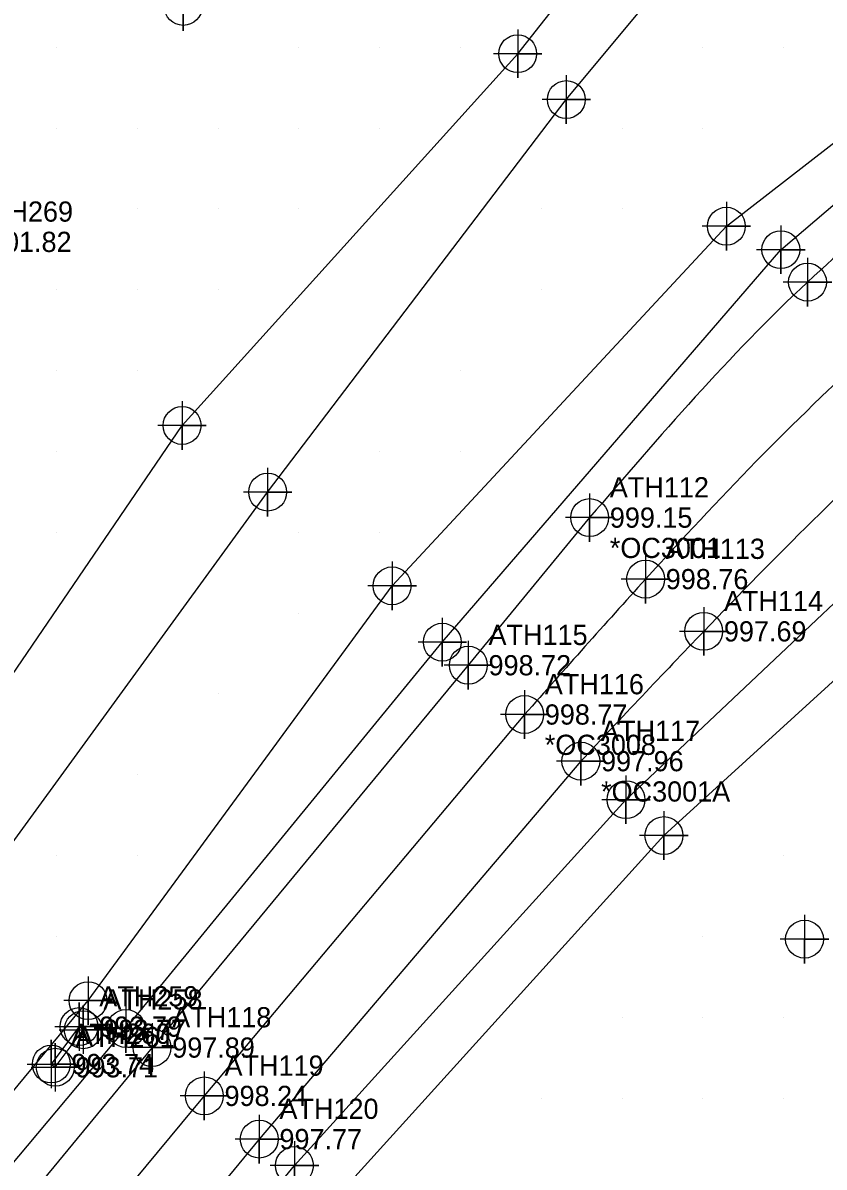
# Model space of a CAD drawing. Extents: x 1116680 to 1117499, y 661040 to 661703.
# Drawn here: x 1116855.8 to 1116955, y 661221.5 to 661363 of the extents above; entities that cross this region are included whole.
import ezdxf

# ---------------------------------------------------------------- set-up
doc = ezdxf.new("R2010")
doc.units = 0
for name, color, linetype in [('Exist DTM Breakline', 7, 'Continuous'), ('Exist DTM Breakline Cogo Point CELL', 7, 'Continuous'), ('Exist DTM Crownline', 7, 'Continuous'), ('Exist DTM Crownline Cogo Comment', 7, 'Continuous'), ('Exist DTM Crownline Cogo Elevation', 7, 'Continuous'), ('Exist DTM Crownline Cogo Number', 7, 'Continuous'), ('Exist DTM Crownline Cogo Point CELL', 7, 'Continuous'), ('Exist DTM QL2 LIDAR Elevation Point', 7, 'Continuous'), ('Exist DTM Regular Point CELL', 7, 'Continuous'), ('Exist DTM Regular Point Cogo Elevation', 7, 'Continuous'), ('Exist DTM Regular Point Cogo Number', 7, 'Continuous'), ('Exist Roads EOP', 7, 'Continuous'), ('Exist Roads EOP Cogo Comment', 7, 'Continuous'), ('Exist Roads EOP Cogo Elevation', 7, 'Continuous'), ('Exist Roads EOP Cogo Number', 7, 'Continuous'), ('Exist Roads EOP Cogo Point CELL', 7, 'Continuous'), ('Exist Structure Major Bridge WW Cogo Elevation', 7, 'Continuous'), ('Exist Structure Major Bridge WW Cogo Number', 7, 'Continuous'), ('Exist Structure Major Bridge WW Cogo Point CELL', 7, 'Continuous')]:
    doc.layers.add(name, color=color, linetype=linetype)

msp = doc.modelspace()

# ---------------------------------------------------------------- linework, layer by layer
at = {"layer": 'Exist DTM Breakline'}
for points in [[(1116759.405, 661157.47), (1116807.255, 661219.832), (1116841.622, 661263.499), (1116875.544, 661313.217), (1116917.082, 661359.208), (1116949.523, 661400.365), (1116973.082, 661430.897), (1117008.611, 661472.228)], [(1116764.746, 661153.381), (1116812.662, 661214.66), (1116849.832, 661255.197), (1116886.132, 661304.973), (1116923.093, 661353.534), (1116959.436, 661397.157), (1116983.43, 661423.245), (1117016.608, 661461.344)], [(1116777.711, 661140.704), (1116828.227, 661198.994), (1116863.907, 661242.056), (1116901.537, 661293.371), (1116942.909, 661337.866), (1116986.207, 661371.481), (1117014.804, 661386.644), (1117027.371, 661386.959)], [(1116764.336, 661115.367), (1116780.79, 661135.76), (1116832.216, 661195.325), (1116868.599, 661238.611), (1116907.746, 661286.411), (1116949.649, 661334.962), (1116977.116, 661358.387), (1117017.083, 661374.758), (1117030.676, 661371.171)], [(1116804.214, 661119.184), (1116852.32, 661176.293), (1116889.45, 661221.661), (1116930.482, 661266.919), (1116979.857, 661313.491), (1117005.659, 661333.608)], [(1116935.96, 661187.155), (1116915.624, 661198.811), (1116892.595, 661215.476), (1116935.176, 661262.478), (1116985.662, 661308.46), (1117011.556, 661329.863)], [(1116863.311, 661238.455), (1116862.795, 661238.847), (1116859.359, 661234.212), (1116859.848, 661233.813), (1116863.311, 661238.455)]]:
    msp.add_lwpolyline(points, dxfattribs=at)
at = {"layer": 'Exist DTM Breakline Cogo Point CELL'}
for points in [[(1116875.69, 661368.058), (1116875.69, 661362.058), (1116875.69, 661365.058), (1116878.69, 661365.058), (1116872.69, 661365.058)], [(1116917.082, 661362.208), (1116917.082, 661356.208), (1116917.082, 661359.208), (1116920.082, 661359.208), (1116914.082, 661359.208)], [(1116923.093, 661356.534), (1116923.093, 661350.534), (1116923.093, 661353.534), (1116926.093, 661353.534), (1116920.093, 661353.534)], [(1116942.909, 661340.866), (1116942.909, 661334.866), (1116942.909, 661337.866), (1116945.909, 661337.866), (1116939.909, 661337.866)], [(1116949.649, 661337.962), (1116949.649, 661331.962), (1116949.649, 661334.962), (1116952.649, 661334.962), (1116946.649, 661334.962)], [(1116875.544, 661316.217), (1116875.544, 661310.217), (1116875.544, 661313.217), (1116878.544, 661313.217), (1116872.544, 661313.217)], [(1116886.132, 661307.973), (1116886.132, 661301.973), (1116886.132, 661304.973), (1116889.132, 661304.973), (1116883.132, 661304.973)], [(1116901.537, 661296.371), (1116901.537, 661290.371), (1116901.537, 661293.371), (1116904.537, 661293.371), (1116898.537, 661293.371)], [(1116907.746, 661289.411), (1116907.746, 661283.411), (1116907.746, 661286.411), (1116910.746, 661286.411), (1116904.746, 661286.411)], [(1116930.482, 661269.919), (1116930.482, 661263.919), (1116930.482, 661266.919), (1116933.482, 661266.919), (1116927.482, 661266.919)], [(1116935.176, 661265.478), (1116935.176, 661259.478), (1116935.176, 661262.478), (1116938.176, 661262.478), (1116932.176, 661262.478)], [(1116863.907, 661245.056), (1116863.907, 661239.056), (1116863.907, 661242.056), (1116866.907, 661242.056), (1116860.907, 661242.056)], [(1116868.599, 661241.611), (1116868.599, 661235.611), (1116868.599, 661238.611), (1116871.599, 661238.611), (1116865.599, 661238.611)], [(1116889.45, 661224.661), (1116889.45, 661218.661), (1116889.45, 661221.661), (1116892.45, 661221.661), (1116886.45, 661221.661)]]:
    msp.add_lwpolyline(points, dxfattribs=at)
for centre in [(1116875.69, 661365.058), (1116917.082, 661359.208), (1116923.093, 661353.534), (1116942.909, 661337.866), (1116949.649, 661334.962), (1116875.544, 661313.217), (1116886.132, 661304.973), (1116901.537, 661293.371), (1116907.746, 661286.411), (1116930.482, 661266.919), (1116935.176, 661262.478), (1116863.907, 661242.056), (1116868.599, 661238.611), (1116889.45, 661221.661)]:
    msp.add_circle(centre, 2.344, dxfattribs=at)
at = {"layer": 'Exist DTM Crownline'}
msp.add_lwpolyline([(1116917.938, 661277.457), (1116878.296, 661230.271), (1116842.354, 661187.006), (1116792.558, 661125.963), (1116776.188, 661106.218)], dxfattribs=at)
msp.add_spline([(1117023.526, 661357.17), (1116985.409, 661341.089), (1116961.036, 661322.674), (1116932.907, 661294.206), (1116917.938, 661277.457)], degree=3, dxfattribs=at)
at = {"layer": 'Exist DTM Crownline Cogo Point CELL'}
for points in [[(1116932.907, 661297.206), (1116932.907, 661291.206), (1116932.907, 661294.206), (1116935.907, 661294.206), (1116929.907, 661294.206)], [(1116917.938, 661280.457), (1116917.938, 661274.457), (1116917.938, 661277.457), (1116920.938, 661277.457), (1116914.938, 661277.457)], [(1116878.296, 661233.271), (1116878.296, 661227.271), (1116878.296, 661230.271), (1116881.296, 661230.271), (1116875.296, 661230.271)]]:
    msp.add_lwpolyline(points, dxfattribs=at)
for centre in [(1116932.907, 661294.206), (1116917.938, 661277.457), (1116878.296, 661230.271)]:
    msp.add_circle(centre, 2.344, dxfattribs=at)
at = {"layer": 'Exist DTM QL2 LIDAR Elevation Point'}
for p, q in [((1116860, 661360), (1116860, 661360)), ((1116890, 661360), (1116890, 661360)), ((1116900, 661360), (1116900, 661360)), ((1116910, 661360), (1116910, 661360)), ((1116940, 661360), (1116940, 661360)), ((1116950, 661360), (1116950, 661360)), ((1116860, 661350), (1116860, 661350)), ((1116870, 661350), (1116870, 661350)), ((1116880, 661350), (1116880, 661350)), ((1116890, 661350), (1116890, 661350)), ((1116900, 661350), (1116900, 661350)), ((1116930, 661350), (1116930, 661350)), ((1116940, 661350), (1116940, 661350)), ((1116860, 661340), (1116860, 661340)), ((1116870, 661340), (1116870, 661340)), ((1116880, 661340), (1116880, 661340)), ((1116890, 661340), (1116890, 661340)), ((1116920, 661340), (1116920, 661340)), ((1116930, 661340), (1116930, 661340)), ((1116860, 661330), (1116860, 661330)), ((1116870, 661330), (1116870, 661330)), ((1116880, 661330), (1116880, 661330)), ((1116920, 661330), (1116920, 661330)), ((1116860, 661320), (1116860, 661320)), ((1116870, 661320), (1116870, 661320)), ((1116910, 661320), (1116910, 661320)), ((1116860, 661310), (1116860, 661310)), ((1116900, 661310), (1116900, 661310)), ((1116910, 661310), (1116910, 661310)), ((1116860, 661300), (1116860, 661300)), ((1116890, 661300), (1116890, 661300)), ((1116900, 661300), (1116900, 661300)), ((1116890, 661290), (1116890, 661290)), ((1116880, 661280), (1116880, 661280)), ((1116870, 661270), (1116870, 661270)), ((1116860, 661260), (1116860, 661260)), ((1116870, 661260), (1116870, 661260)), ((1116950, 661260), (1116950, 661260)), ((1116860, 661250), (1116860, 661250)), ((1116940, 661250), (1116940, 661250)), ((1116950, 661250), (1116950, 661250)), ((1116930, 661240), (1116930, 661240)), ((1116940, 661240), (1116940, 661240)), ((1116950, 661240), (1116950, 661240)), ((1116920, 661230), (1116920, 661230)), ((1116930, 661230), (1116930, 661230)), ((1116940, 661230), (1116940, 661230)), ((1116950, 661230), (1116950, 661230))]:
    msp.add_line(p, q, dxfattribs=at)
at = {"layer": 'Exist DTM Regular Point CELL'}
msp.add_lwpolyline([(1116952.58, 661252.659), (1116952.58, 661246.659), (1116952.58, 661249.659), (1116955.58, 661249.659), (1116949.58, 661249.659)], dxfattribs=at)
msp.add_circle((1116952.58, 661249.659), 2.344, dxfattribs=at)
at = {"layer": 'Exist Roads EOP'}
for points in [[(1116925.984, 661301.817), (1116910.969, 661283.553), (1116871.822, 661236.252), (1116835.673, 661192.44), (1116785.819, 661131.962), (1116768.893, 661111.563)], [(1116924.898, 661271.684), (1116885.096, 661224.926), (1116849.016, 661181.231), (1116799.444, 661121.119), (1116782.519, 661100.642)]]:
    msp.add_lwpolyline(points, dxfattribs=at)
for points in [[(1117026.904, 661368.114), (1116980.178, 661351.152), (1116952.946, 661330.95), (1116925.984, 661301.817)], [(1117018.008, 661346.187), (1116990.857, 661332.639), (1116967.617, 661314.642), (1116940.103, 661287.744), (1116924.898, 661271.684)]]:
    msp.add_spline(points, degree=3, dxfattribs=at)
at = {"layer": 'Exist Roads EOP Cogo Point CELL'}
for points in [[(1116952.946, 661333.95), (1116952.946, 661327.95), (1116952.946, 661330.95), (1116955.946, 661330.95), (1116949.946, 661330.95)], [(1116925.984, 661304.817), (1116925.984, 661298.817), (1116925.984, 661301.817), (1116928.984, 661301.817), (1116922.984, 661301.817)], [(1116940.103, 661290.744), (1116940.103, 661284.744), (1116940.103, 661287.744), (1116943.103, 661287.744), (1116937.103, 661287.744)], [(1116910.969, 661286.553), (1116910.969, 661280.553), (1116910.969, 661283.553), (1116913.969, 661283.553), (1116907.969, 661283.553)], [(1116924.898, 661274.684), (1116924.898, 661268.684), (1116924.898, 661271.684), (1116927.898, 661271.684), (1116921.898, 661271.684)], [(1116871.822, 661239.252), (1116871.822, 661233.252), (1116871.822, 661236.252), (1116874.822, 661236.252), (1116868.822, 661236.252)], [(1116885.096, 661227.926), (1116885.096, 661221.926), (1116885.096, 661224.926), (1116888.096, 661224.926), (1116882.096, 661224.926)]]:
    msp.add_lwpolyline(points, dxfattribs=at)
for centre in [(1116952.946, 661330.95), (1116925.984, 661301.817), (1116940.103, 661287.744), (1116910.969, 661283.553), (1116924.898, 661271.684), (1116871.822, 661236.252), (1116885.096, 661224.926)]:
    msp.add_circle(centre, 2.344, dxfattribs=at)
at = {"layer": 'Exist Structure Major Bridge WW Cogo Point CELL'}
for points in [[(1116859.795, 661238.847), (1116865.795, 661238.847), (1116862.795, 661238.847), (1116862.795, 661241.847), (1116862.795, 661235.847)], [(1116860.311, 661238.455), (1116866.311, 661238.455), (1116863.311, 661238.455), (1116863.311, 661241.455), (1116863.311, 661235.455)], [(1116856.359, 661234.212), (1116862.359, 661234.212), (1116859.359, 661234.212), (1116859.359, 661237.212), (1116859.359, 661231.212)], [(1116856.848, 661233.813), (1116862.848, 661233.813), (1116859.848, 661233.813), (1116859.848, 661236.813), (1116859.848, 661230.813)]]:
    msp.add_lwpolyline(points, dxfattribs=at)
for centre in [(1116862.795, 661238.847), (1116863.311, 661238.455), (1116859.359, 661234.212), (1116859.848, 661233.813)]:
    msp.add_circle(centre, 2.344, dxfattribs=at)

# ---------------------------------------------------------------- texts
at = {"layer": 'Exist DTM Crownline Cogo Comment'}
msp.add_text('*OC3008', height=2.5, dxfattribs=at).set_placement((1116920.438, 661272.457))
at = {"layer": 'Exist DTM Crownline Cogo Elevation'}
for s, p in [('998.76', (1116935.407, 661292.956)), ('998.77', (1116920.438, 661276.207)), ('998.24', (1116880.796, 661229.021))]:
    msp.add_text(s, height=2.5, dxfattribs=at).set_placement(p)
at = {"layer": 'Exist DTM Crownline Cogo Number'}
for s, p in [('ATH113', (1116935.407, 661296.706)), ('ATH116', (1116920.438, 661279.957)), ('ATH119', (1116880.796, 661232.771))]:
    msp.add_text(s, height=2.5, dxfattribs=at).set_placement(p)
at = {"layer": 'Exist DTM Regular Point Cogo Elevation'}
msp.add_text('1001.82', height=2.5, dxfattribs=at).set_placement((1116849.783, 661334.68))
at = {"layer": 'Exist DTM Regular Point Cogo Number'}
msp.add_text('ATH269', height=2.5, dxfattribs=at).set_placement((1116849.783, 661338.43))
at = {"layer": 'Exist Roads EOP Cogo Comment'}
for s, p in [('*OC3001', (1116928.484, 661296.817)), ('*OC3001A', (1116927.398, 661266.684))]:
    msp.add_text(s, height=2.5, dxfattribs=at).set_placement(p)
at = {"layer": 'Exist Roads EOP Cogo Elevation'}
for s, p in [('999.15', (1116928.484, 661300.567)), ('997.69', (1116942.603, 661286.494)), ('998.72', (1116913.469, 661282.303)), ('997.96', (1116927.398, 661270.434)), ('997.89', (1116874.322, 661235.002)), ('997.77', (1116887.596, 661223.676))]:
    msp.add_text(s, height=2.5, dxfattribs=at).set_placement(p)
at = {"layer": 'Exist Roads EOP Cogo Number'}
for s, p in [('ATH112', (1116928.484, 661304.317)), ('ATH114', (1116942.603, 661290.244)), ('ATH115', (1116913.469, 661286.053)), ('ATH117', (1116927.398, 661274.184)), ('ATH118', (1116874.322, 661238.752)), ('ATH120', (1116887.596, 661227.426))]:
    msp.add_text(s, height=2.5, dxfattribs=at).set_placement(p)
at = {"layer": 'Exist Structure Major Bridge WW Cogo Elevation'}
for s, p in [('993.79', (1116865.295, 661237.597)), ('993.77', (1116865.811, 661237.205)), ('993.74', (1116861.859, 661232.962)), ('993.71', (1116862.348, 661232.563))]:
    msp.add_text(s, height=2.5, dxfattribs=at).set_placement(p)
at = {"layer": 'Exist Structure Major Bridge WW Cogo Number'}
for s, p in [('ATH259', (1116865.295, 661241.347)), ('ATH258', (1116865.811, 661240.955)), ('ATH260', (1116861.859, 661236.712)), ('ATH261', (1116862.348, 661236.313))]:
    msp.add_text(s, height=2.5, dxfattribs=at).set_placement(p)

doc.saveas('drawing.dxf')
